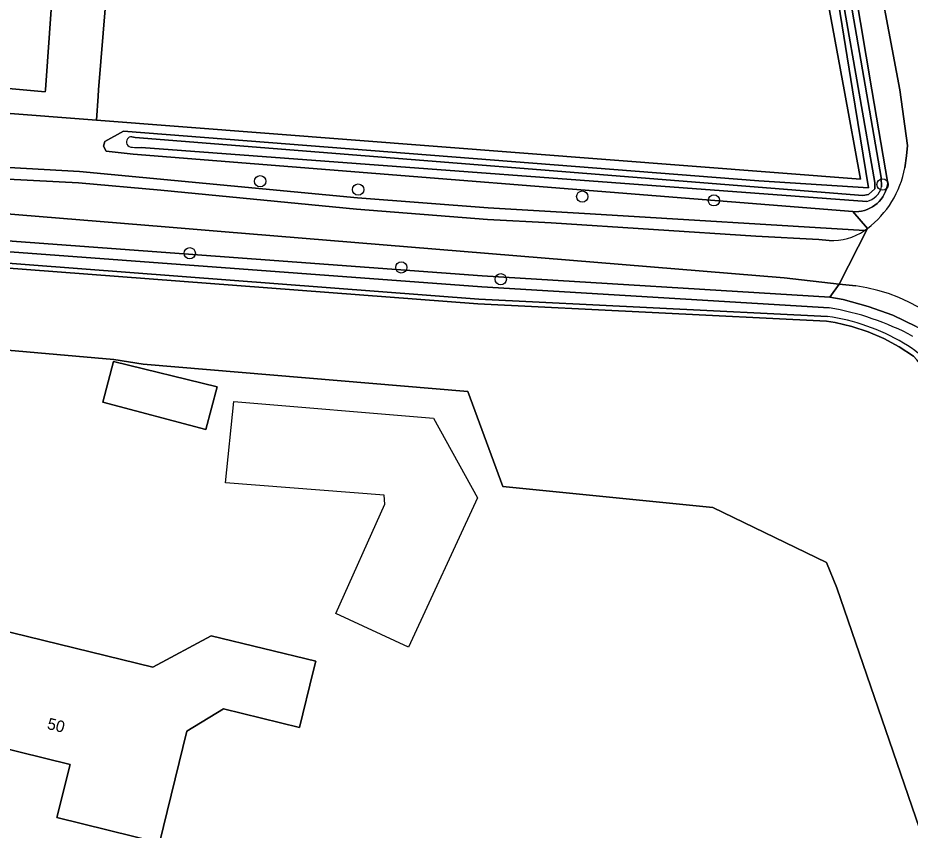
# Model space of a CAD drawing. Extents: x 162722 to 165104, y 384719 to 386284.
# Drawn here: x 164060.8 to 164137.9, y 385185.9 to 385256.2 of the extents above; entities that cross this region are included whole.
import ezdxf

# ---------------------------------------------------------------- set-up
doc = ezdxf.new("R2010")
doc.units = 0
for name, color, linetype in [('IMGEO_Boom', 7, 'Continuous'), ('IMGEO_Erf', 7, 'Continuous'), ('IMGEO_Gemengd_bos', 7, 'Continuous'), ('IMGEO_Grasland_agrarisch', 7, 'Continuous'), ('IMGEO_Groenvoorziening', 7, 'Continuous'), ('IMGEO_Loofbos', 7, 'Continuous'), ('IMGEO_Oever', 7, 'Continuous'), ('IMGEO_Pand', 7, 'Continuous'), ('IMGEO_Pand_nummerreeks', 7, 'Continuous'), ('IMGEO_Pand_vergunning_verleend', 7, 'Continuous'), ('IMGEO_Rijbaan_lokaal_halfverhard', 7, 'Continuous'), ('IMGEO_Voetpad_halfverhard', 7, 'Continuous'), ('IMGEO_Waterloop', 7, 'Continuous')]:
    doc.layers.add(name, color=color, linetype=linetype)

msp = doc.modelspace()

# ---------------------------------------------------------------- linework, layer by layer
at = {"layer": 'IMGEO_Boom'}
for centre in [(164081.716, 385242.092), (164090.193, 385241.372), (164135.555, 385241.813), (164109.581, 385240.771), (164120.967, 385240.443), (164075.626, 385235.86), (164093.928, 385234.638), (164102.53, 385233.612)]:
    msp.add_circle(centre, 0.489, dxfattribs=at)
at = {"layer": 'IMGEO_Erf'}
for points in [[(164131.602, 385206.911), (164130.709, 385209.106), (164120.887, 385213.868), (164102.708, 385215.684), (164099.681, 385223.884), (164071.605, 385226.264), (164069.058, 385226.655), (164000.03, 385232.739), (163994.489, 385233.421), (163921.241, 385240.035), (163917.358, 385195.848), (163948.65, 385193.052), (163953.489, 385192.612), (163997.498, 385188.685), (164000, 385188.451), (164002.51, 385188.217), (164009.05, 385187.592)], [(164036.204, 385181.139), (164039.945, 385179.482), (164072.64, 385164.57), (164078.669, 385161.813), (164095.502, 385154.125), (164099.033, 385152.538), (164099.324, 385152.404), (164101.923, 385153.628), (164120.431, 385163.473), (164142.636, 385174.734), (164131.602, 385206.911)]]:
    msp.add_lwpolyline(points, dxfattribs=at)
for points in [[(164069.043, 385226.496), (164078.001, 385224.313), (164077.014, 385220.612), (164068.107, 385222.987)], [(164056.483, 385193.765), (164057.675, 385198.621), (164058.841, 385203.369), (164072.423, 385200.034), (164077.494, 385202.759), (164086.519, 385200.543), (164086.305, 385199.67), (164085.112, 385194.814), (164078.547, 385196.425), (164075.387, 385194.511), (164073.011, 385184.835), (164064.141, 385187.013), (164065.269, 385191.608)]]:
    msp.add_lwpolyline(points, close=True, dxfattribs=at)
at = {"layer": 'IMGEO_Gemengd_bos'}
for points in [[(164156.151, 385178.3), (164153.536, 385189.825), (164152.377, 385189.32), (164140.969, 385222.37), (164140.637, 385223.303), (164140.223, 385224.202), (164139.73, 385225.06), (164139.163, 385225.871), (164138.525, 385226.629), (164138.221, 385226.946), (164136.982, 385227.768), (164135.675, 385228.476), (164134.31, 385229.064), (164132.898, 385229.528), (164131.451, 385229.864), (164130.707, 385229.984), (164100.555, 385231.49), (164022.811, 385237.414)], [(164000.03, 385232.739), (164069.058, 385226.655), (164071.605, 385226.264), (164099.681, 385223.884), (164102.708, 385215.684), (164120.887, 385213.868), (164130.709, 385209.106), (164131.602, 385206.911), (164142.636, 385174.734)]]:
    msp.add_lwpolyline(points, dxfattribs=at)
at = {"layer": 'IMGEO_Grasland_agrarisch'}
for points in [[(164112.735, 385355.591), (164107.042, 385383.651), (164105.836, 385388.319), (164079.155, 385390.239), (164078.907, 385386.133), (164075.255, 385341.588), (164071.395, 385294.516), (164067.745, 385250), (164067.7, 385249.457), (164067.556, 385247.378), (164133.654, 385242.284), (164132.23, 385250)], [(164066.331, 385295.018), (164004.391, 385300.416), (164000, 385300.799), (163979.59, 385302.533), (163976.141, 385257.739), (164063.131, 385249.845), (164063.142, 385250)]]:
    msp.add_lwpolyline(points, close=True, dxfattribs=at)
at = {"layer": 'IMGEO_Groenvoorziening'}
for points in [[(164133.984, 385237.821), (164110.27, 385239.269), (164101.434, 385239.792), (164090.145, 385240.675), (164066.084, 385242.942), (164059.968, 385243.285), (164029.39, 385245.491), (164014.816, 385246.893), (164010.318, 385247.545), (164003.336, 385247.856), (163985.761, 385249.378), (163964.707, 385250.985), (163945.645, 385252.441), (163930.503, 385253.597), (163921.295, 385254.477), (163910.058, 385255.424), (163896.001, 385257.12)], [(164022.687, 385239.688), (164100.917, 385233.898), (164130.998, 385232.074), (164131.796, 385233.176), (164127.033, 385233.75), (164078.338, 385237.745), (164073.508, 385238.141), (164000, 385244.172)], [(164059.896, 385242.288), (164065.997, 385241.946), (164073.136, 385241.319), (164090.049, 385239.68), (164101.378, 385238.794), (164106.897, 385238.487), (164124.606, 385237.331), (164130.028, 385237.061), (164130.931, 385236.981)], [(164133.245, 385233.033), (164131.796, 385233.176), (164130.998, 385232.074), (164132.149, 385231.848), (164134.323, 385231.266), (164136.438, 385230.492), (164138.474, 385229.532), (164138.799, 385229.341), (164139.521, 385228.852), (164140.197, 385228.3), (164140.82, 385227.69), (164141.387, 385227.027), (164141.892, 385226.316), (164142.332, 385225.563), (164142.702, 385224.773), (164143.001, 385223.954), (164143.225, 385223.111), (164145.487, 385216.791), (164152.619, 385195.851), (164153.989, 385192.207), (164154.695, 385190.33), (164153.536, 385189.825), (164156.151, 385178.3)]]:
    msp.add_lwpolyline(points, dxfattribs=at)
for centre, radius, start, end in [((164131.248, 385241.795), 4.825, 266.22785, 304.53948), ((164131.339, 385218.607), 14.552, 22.21351, 82.47475)]:
    msp.add_arc(centre, radius, start, end, dxfattribs=at)
at = {"layer": 'IMGEO_Loofbos'}
for points in [[(164134.243, 385238.013), (164132.992, 385239.466), (164070.719, 385244.434), (164068.398, 385244.692), (164068.174, 385245.13), (164068.29, 385245.531), (164069.9, 385246.426), (164124.85, 385242.129), (164134.351, 385241.519), (164132.941, 385250), (164131.602, 385258.431), (164130.482, 385264.461), (164125.25, 385291.909), (164112.735, 385355.591), (164132.23, 385250), (164133.654, 385242.284), (164067.556, 385247.378)], [(164137.488, 385243.269), (164137.626, 385244.292), (164137.698, 385245.189), (164137.044, 385250), (164134.487, 385263.658)], [(164133.157, 385258.792), (164134.639, 385250), (164136.002, 385241.913), (164135.961, 385241.678), (164135.896, 385241.434), (164135.81, 385241.197), (164135.703, 385240.968), (164135.576, 385240.75), (164135.43, 385240.545), (164135.266, 385240.353), (164135.085, 385240.176), (164134.89, 385240.017), (164134.681, 385239.875), (164134.46, 385239.753), (164134.23, 385239.651), (164133.991, 385239.57), (164133.746, 385239.51), (164133.496, 385239.473), (164133.244, 385239.458), (164132.992, 385239.466), (164134.243, 385238.013)], [(164067.556, 385247.378), (164033.541, 385250), (164000, 385252.585), (163970.67, 385255.015), (163934.452, 385258.016)], [(163896.001, 385257.12), (163910.058, 385255.424), (163921.295, 385254.477), (163930.503, 385253.597), (163945.645, 385252.441), (163964.707, 385250.985), (163985.761, 385249.378), (164003.336, 385247.856), (164010.318, 385247.545), (164014.816, 385246.893), (164029.39, 385245.491), (164059.968, 385243.285), (164066.084, 385242.942), (164090.145, 385240.675), (164101.434, 385239.792), (164110.27, 385239.269), (164133.984, 385237.821)]]:
    msp.add_lwpolyline(points, dxfattribs=at)
msp.add_lwpolyline([(164071.395, 385294.516), (164066.331, 385295.018), (164063.142, 385250), (164063.131, 385249.845), (163976.141, 385257.739), (163979.59, 385302.533), (163974.779, 385302.886), (163970.961, 385258.245), (163970.67, 385255.015), (164000, 385252.585), (164033.541, 385250), (164067.556, 385247.378), (164067.7, 385249.457), (164067.745, 385250)], close=True, dxfattribs=at)
for centre, radius, start, end in [((164129.165, 385244.778), 8.458, 306.8928, 349.72569), ((164131.019, 385242.091), 5.199, 304.77304, 308.32698)]:
    msp.add_arc(centre, radius, start, end, dxfattribs=at)
at = {"layer": 'IMGEO_Oever'}
for points in [[(164131.602, 385258.431), (164132.941, 385250), (164134.351, 385241.519), (164124.85, 385242.129), (164069.9, 385246.426), (164068.29, 385245.531), (164068.174, 385245.13), (164068.398, 385244.692), (164070.719, 385244.434), (164132.992, 385239.466), (164133.244, 385239.458), (164133.496, 385239.473), (164133.746, 385239.51), (164133.991, 385239.57), (164134.23, 385239.651), (164134.46, 385239.753), (164134.681, 385239.875), (164134.89, 385240.017), (164135.085, 385240.176), (164135.266, 385240.353), (164135.43, 385240.545), (164135.576, 385240.75), (164135.703, 385240.968), (164135.81, 385241.197), (164135.896, 385241.434), (164135.961, 385241.678), (164136.002, 385241.913), (164134.639, 385250), (164133.157, 385258.792)], [(164070.609, 385245.937), (164070.762, 385245.922), (164070.92, 385245.893), (164133.838, 385240.861), (164134.341, 385240.943), (164134.89, 385241.441), (164134.89, 385241.989), (164132.177, 385257.467)], [(164132.707, 385257.822), (164132.749, 385257.744), (164132.818, 385257.561), (164135.437, 385242.424), (164135.475, 385241.624)], [(163916.319, 385246.927), (163999.97, 385239.734), (164009.213, 385238.961), (164022.683, 385238.747), (164100.898, 385232.958), (164130.939, 385231.136)], [(164130.804, 385230.389), (164100.624, 385231.896), (164022.869, 385237.821), (164009.308, 385238.049), (164000.083, 385238.825), (163921.9, 385245.405), (163916.393, 385245.866)], [(164134.185, 385240.347), (164071.417, 385245.016)], [(164138.474, 385229.532), (164136.438, 385230.492), (164134.323, 385231.266), (164132.149, 385231.848), (164130.998, 385232.074), (164100.917, 385233.898), (164022.687, 385239.688)], [(164022.811, 385237.414), (164100.555, 385231.49), (164130.707, 385229.984), (164131.451, 385229.864), (164132.898, 385229.528), (164134.31, 385229.064), (164135.675, 385228.476), (164136.982, 385227.768), (164138.221, 385226.946)]]:
    msp.add_lwpolyline(points, dxfattribs=at)
for centre, radius, start, end in [((164070.642, 385245.483), 0.488, 145.56621, 199.67119), ((164070.577, 385245.531), 0.407, 85.53577, 145.96814), ((164070.657, 385245.591), 0.547, 209.87272, 271.99834), ((164071.275, 385250.869), 5.855, 264.12783, 271.38977), ((164133.775, 385242.052), 1.753, 283.53402, 345.88567), ((164127.084, 385207.948), 23.507, 61.82038, 80.56176), ((164128.44, 385213.226), 17.325, 59.02269, 82.1567), ((164134.137, 385221.998), 6.882, 35.71446, 62.10582)]:
    msp.add_arc(centre, radius, start, end, dxfattribs=at)
at = {"layer": 'IMGEO_Pand'}
for points in [[(164069.043, 385226.496), (164068.107, 385222.987), (164077.014, 385220.612), (164078.001, 385224.313)], [(164056.483, 385193.765), (164065.269, 385191.608), (164064.141, 385187.013), (164073.011, 385184.835), (164075.387, 385194.511), (164078.547, 385196.425), (164085.112, 385194.814), (164086.305, 385199.67), (164086.519, 385200.543), (164077.494, 385202.759), (164072.423, 385200.034), (164058.841, 385203.369), (164057.675, 385198.621)]]:
    msp.add_lwpolyline(points, close=True, dxfattribs=at)
at = {"layer": 'IMGEO_Pand_vergunning_verleend'}
msp.add_lwpolyline([(164078.709, 385215.993), (164079.443, 385223.025), (164096.704, 385221.576), (164100.528, 385214.705), (164094.551, 385201.78), (164088.261, 385204.689), (164092.494, 385214.138), (164092.433, 385214.926)], close=True, dxfattribs=at)
at = {"layer": 'IMGEO_Rijbaan_lokaal_halfverhard'}
for points in [[(164029.318, 385244.494), (164023.585, 385244.906), (164014.673, 385245.903), (164010.175, 385246.555), (164003.275, 385246.864), (163986.232, 385248.339), (163964.631, 385249.988), (163959.286, 385250.396), (163945.569, 385251.444), (163930.408, 385252.602), (163921.2, 385253.482), (163916.03, 385253.917), (163915.816, 385251.483), (163930.032, 385250), (163974.962, 385246.024), (163992.795, 385244.603), (164000, 385244.172), (164073.508, 385238.141), (164078.338, 385237.745), (164127.033, 385233.75), (164131.796, 385233.176), (164134.243, 385238.013)], [(164130.931, 385236.981), (164130.028, 385237.061), (164124.606, 385237.331), (164106.897, 385238.487), (164101.378, 385238.794), (164090.049, 385239.68), (164073.136, 385241.319), (164065.997, 385241.946), (164059.896, 385242.288), (164029.318, 385244.494)]]:
    msp.add_lwpolyline(points, dxfattribs=at)
for centre, radius, start, end in [((164131.019, 385242.091), 5.199, 304.77304, 308.32698), ((164131.248, 385241.795), 4.825, 266.22785, 304.53948)]:
    msp.add_arc(centre, radius, start, end, dxfattribs=at)
at = {"layer": 'IMGEO_Voetpad_halfverhard'}
for points in [[(164109.878, 385387.837), (164114.146, 385366.839), (164134.487, 385263.658), (164137.044, 385250), (164137.698, 385245.189), (164137.626, 385244.292), (164137.488, 385243.269)], [(164134.243, 385238.013), (164131.796, 385233.176), (164133.245, 385233.033)]]:
    msp.add_lwpolyline(points, dxfattribs=at)
for centre, radius, start, end in [((164129.165, 385244.778), 8.458, 306.8928, 349.72569), ((164131.339, 385218.607), 14.552, 22.21351, 82.47475)]:
    msp.add_arc(centre, radius, start, end, dxfattribs=at)
at = {"layer": 'IMGEO_Waterloop'}
for points in [[(164132.174, 385257.622), (164132.177, 385257.467), (164134.89, 385241.989), (164134.89, 385241.441), (164134.341, 385240.943), (164133.838, 385240.861), (164070.92, 385245.893)], [(164135.475, 385241.624), (164135.437, 385242.424), (164132.818, 385257.561), (164132.749, 385257.744), (164132.707, 385257.822)], [(164130.939, 385231.136), (164100.898, 385232.958), (164022.683, 385238.747), (164009.213, 385238.961), (163999.97, 385239.734), (163916.319, 385246.927)], [(163916.393, 385245.866), (163921.9, 385245.405), (164000.083, 385238.825), (164009.308, 385238.049), (164022.869, 385237.821), (164100.624, 385231.896), (164130.804, 385230.389)], [(164070.92, 385245.893), (164070.762, 385245.922), (164070.609, 385245.937)], [(164071.417, 385245.016), (164134.185, 385240.347)]]:
    msp.add_lwpolyline(points, dxfattribs=at)
for centre, radius, start, end in [((164070.642, 385245.483), 0.488, 145.56621, 199.67119), ((164070.577, 385245.531), 0.407, 85.53577, 145.96814), ((164070.657, 385245.591), 0.547, 209.87272, 271.99834), ((164071.275, 385250.869), 5.855, 264.12783, 271.38977), ((164133.775, 385242.052), 1.753, 283.53402, 345.88567), ((164127.084, 385207.948), 23.507, 61.82038, 80.56176), ((164128.44, 385213.226), 17.325, 59.02269, 82.1567), ((164134.137, 385221.998), 6.882, 35.71446, 62.10582)]:
    msp.add_arc(centre, radius, start, end, dxfattribs=at)

# ---------------------------------------------------------------- texts
at = {"layer": 'IMGEO_Pand_nummerreeks'}
msp.add_text('50', height=1, rotation=346.20645, dxfattribs=at).set_placement((164063.229, 385194.703))

doc.saveas('drawing.dxf')
